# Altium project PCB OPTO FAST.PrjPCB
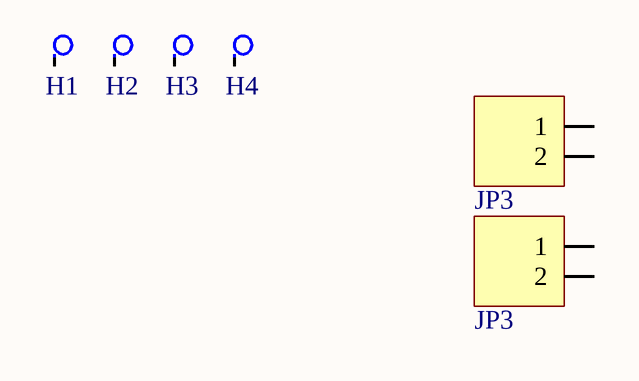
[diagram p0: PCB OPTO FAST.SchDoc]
1 sheet, 6 parts. Net scope: global (net labels, ports and power ports of the same name join across sheets).
Board file: PCB1.PcbDoc

## Sheet PCB OPTO FAST.SchDoc
size A

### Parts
(Parts that share a designator on the sheet are numbered #1, #2 ... from top to bottom, then left to right.)
H1  Agujero de Montaje  [agujero]  (value not drawn)  (no BOM)
H2  Agujero de Montaje  [agujero]  (value not drawn)  (no BOM)
H3  Agujero de Montaje  [agujero]  (value not drawn)  (no BOM)
H4  Agujero de Montaje  [agujero]  (value not drawn)  (no BOM)
JP3#1  Header2x1  [CONPOL2X1]  (value not drawn)
JP3#2  Header2x1  [CONPOL2X1]  (value not drawn)

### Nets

Not connected (* = marked no-connect by the designer): H1 1; H2 1; H3 1; H4 1; JP3#1 1 2; JP3#2 1 2

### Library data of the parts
JP3#1 JP3#2 = Header2x1: Header 2x1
